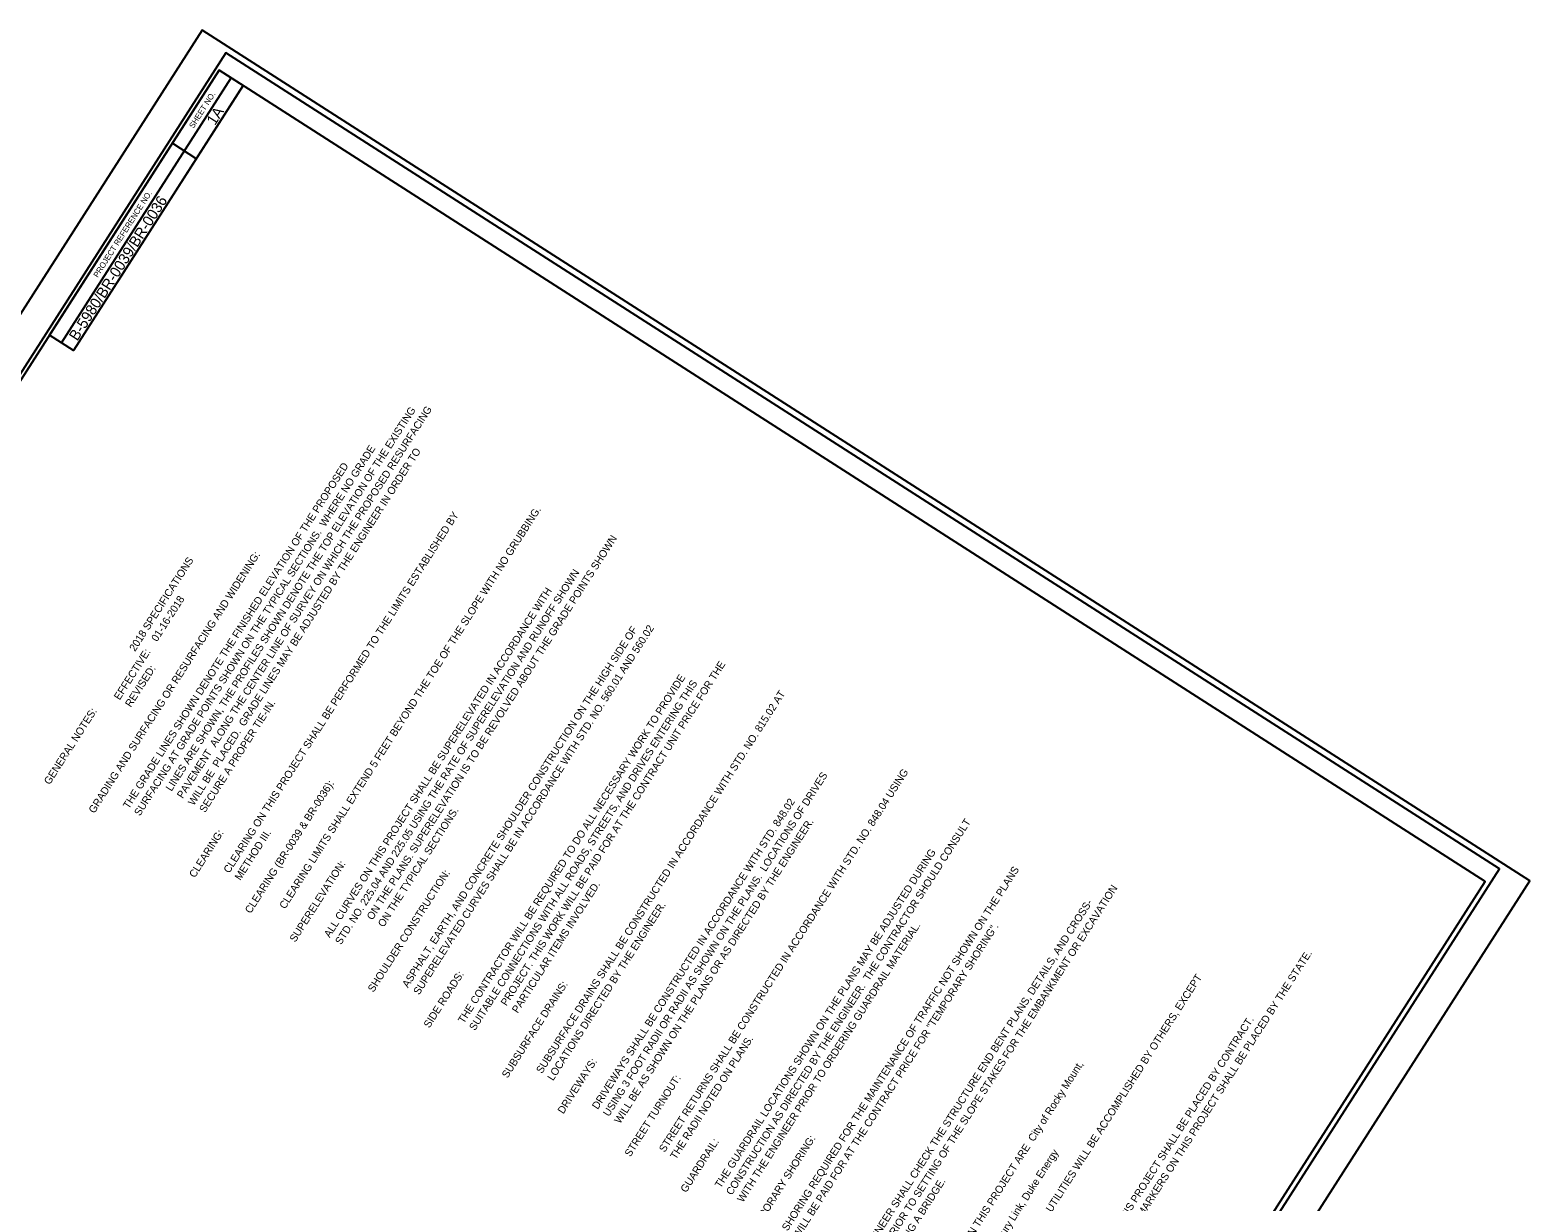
# Model space of a CAD drawing. Extents: x 2347249 to 2361994, y 830101 to 846299.
# Drawn here: x 2353623 to 2361994, y 839761 to 846299 of the extents above; entities that cross this region are included whole.
import ezdxf

# ---------------------------------------------------------------- set-up
doc = ezdxf.new("R2010")
doc.units = 0
for name, color, linetype in [('Sheet Data Field CELL', 7, 'Continuous'), ('Sheet Plot Border Inside CELL', 7, 'Continuous'), ('Sheet Plot Border Outside CELL', 7, 'Continuous'), ('Sheet Symbology CELL', 7, 'Continuous')]:
    doc.layers.add(name, color=color, linetype=linetype)

msp = doc.modelspace()

# ---------------------------------------------------------------- linework, layer by layer
at = {"layer": 'Sheet Plot Border Inside CELL'}
msp.add_lwpolyline([(2354564.1, 830285.9), (2361823.6, 841618.9), (2354715.9, 846171.7), (2347456.5, 834838.7)], close=True, dxfattribs=at)
at = {"layer": 'Sheet Plot Border Outside CELL'}
msp.add_lwpolyline([(2354658.7, 830100.6), (2361994.4, 841552.6), (2354584.3, 846299.2), (2347248.6, 834847.2)], close=True, dxfattribs=at)
at = {"layer": 'Sheet Symbology CELL'}
for p, q in [((2353799.3, 844554.1), (2354746.3, 846032.4)), ((2354116.5, 844900.9), (2354813.6, 845989.2)), ((2354417.5, 845667.5), (2354552.3, 845581.2))]:
    msp.add_line(p, q, dxfattribs=at)
for points in [[(2354678.6, 846075.7), (2348144.5, 835875), (2355211, 831348.5), (2361745.1, 841549.2)], [(2353731.7, 844597.4), (2354678.6, 846075.7), (2354813.6, 845989.2), (2353866.7, 844511)]]:
    msp.add_lwpolyline(points, close=True, dxfattribs=at)

# ---------------------------------------------------------------- texts
at = {"layer": 'Sheet Data Field CELL'}
for s, height, p in [('1A', 60, (2354655.1, 845763.4)), ('B-5980/BR-0039/BR-0036', 60, (2353886.9, 844560.6)), ('LINES ARE SHOWN, THE PROFILES SHOWN DENOTE THE TOP ELEVATION OF THE EXISTING ', 42, (2354412.7, 842048.7)), ('PAVEMENT  ALONG THE CENTER LINE OF SURVEY ON WHICH THE PROPOSED RESURFACING ', 42, (2354475, 842008.8)), ('        SURFACING AT GRADE POINTS SHOWN ON THE TYPICAL SECTIONS.  WHERE NO GRADE ', 42, (2354169.1, 841805.7)), ('WILL BE  PLACED.  GRADE LINES MAY BE ADJUSTED BY THE ENGINEER IN ORDER TO ', 42, (2354537.3, 841968.9)), ('        THE GRADE LINES SHOWN DENOTE THE FINISHED ELEVATION OF THE PROPOSED ', 42, (2354106.8, 841845.6)), ('        CLEARING ON THIS PROJECT SHALL BE PERFORMED TO THE LIMITS ESTABLISHED BY ', 42, (2354667.7, 841486.4)), ('        CLEARING LIMITS SHALL EXTEND 5 FEET BEYOND THE TOE OF THE SLOPE WITH NO GRUBBING.', 42, (2354979.3, 841286.8)), ('ON THE PLANS. SUPERELEVATION IS TO BE REVOLVED ABOUT THE GRADE POINTS SHOWN ', 42, (2355534.4, 841330.2)), ('GENERAL NOTES:                         2018 SPECIFICATIONS', 42, (2353732.9, 842085.2)), ('GRADING AND SURFACING OR RESURFACING AND WIDENING:  ', 42, (2353982.1, 841925.5)), ('        STD. NO. 225.04 AND 225.05 USING THE RATE OF SUPERELEVATION AND RUNOFF SHOWN ', 42, (2355290.9, 841087.2)), ('        ALL CURVES ON THIS PROJECT SHALL BE SUPERELEVATED IN ACCORDANCE WITH', 42, (2355228.5, 841127.1)), ('                                       EFFECTIVE:    01-16-2018', 42, (2353795.2, 842045.2)), ('        ASPHALT, EARTH, AND CONCRETE SHOULDER CONSTRUCTION ON THE HIGH SIDE OF', 42, (2355664.8, 840847.7)), ('        SUPERELEVATED CURVES SHALL BE IN ACCORDANCE WITH STD. NO. 560.01 AND 560.02', 42, (2355727.1, 840807.7)), ('                                       REVISED:      ', 42, (2353857.5, 842005.3)), ('PROJECT. THIS WORK WILL BE PAID FOR AT THE CONTRACT UNIT PRICE FOR THE ', 42, (2356282.3, 840851.2)), ('        THE CONTRACTOR WILL BE REQUIRED TO DO ALL NECESSARY WORK TO PROVIDE ', 42, (2355976.4, 840648.1)), ('        SUITABLE CONNECTIONS WITH ALL ROADS, STREETS, AND DRIVES ENTERING THIS ', 42, (2356038.7, 840608.1)), ('        SUBSURFACE DRAINS SHALL BE CONSTRUCTED IN ACCORDANCE WITH STD. NO. 815.02 AT ', 42, (2356412.6, 840368.6)), ('SECURE A PROPER TIE-IN.  ', 42, (2354599.6, 841929)), ('        USING 3 FOOT RADII OR RADII AS SHOWN ON THE PLANS.  LOCATIONS OF DRIVES', 42, (2356786.6, 840129.1)), ('        STREET RETURNS SHALL BE CONSTRUCTED IN ACCORDANCE WITH STD. NO. 848.04 USING ', 42, (2357098.2, 839929.5)), ('CLEARING (BR-0039 & BR-0036):  ', 42, (2354854.6, 841366.6)), ('        DRIVEWAYS SHALL BE CONSTRUCTED IN ACCORDANCE WITH STD. 848.02', 42, (2356724.2, 840169)), ('ON THE TYPICAL SECTIONS.  ', 42, (2355596.7, 841290.3)), ('CLEARING:  ', 42, (2354543, 841566.2)), ('        METHOD III.', 42, (2354730, 841446.5)), ('        WILL BE AS SHOWN ON THE PLANS OR AS DIRECTED BY THE ENGINEER.  ', 42, (2356848.9, 840089.2)), ('        CONSTRUCTION AS DIRECTED BY THE ENGINEER.  THE CONTRACTOR SHOULD CONSULT', 42, (2357472.1, 839690)), ('SUPERELEVATION:  ', 42, (2355103.9, 841206.9)), ('        THE GUARDRAIL LOCATIONS SHOWN ON THE PLANS MAY BE ADJUSTED DURING ', 42, (2357409.8, 839729.9)), ('SHOULDER CONSTRUCTION:  ', 42, (2355540.1, 840927.5)), ('        SHORING REQUIRED FOR THE MAINTENANCE OF TRAFFIC NOT SHOWN ON THE PLANS ', 42, (2357783.7, 839490.4)), ('PARTICULAR ITEMS INVOLVED.  ', 42, (2356344.6, 840811.2)), ('        SECTION PRIOR TO SETTING OF THE SLOPE STAKES FOR THE EMBANKMENT OR EXCAVATION ', 42, (2358219.9, 839211)), ('        LOCATIONS DIRECTED BY THE ENGINEER.  ', 42, (2356474.9, 840328.7)), ('        THE ENGINEER SHALL CHECK THE STRUCTURE END BENT PLANS, DETAILS, AND CROSS-', 42, (2358157.6, 839250.9)), ('        WITH THE ENGINEER PRIOR TO ORDERING GUARDRAIL MATERIAL.', 42, (2357534.4, 839650.1)), ('        WILL BE PAID FOR AT THE CONTRACT PRICE FOR "TEMPORARY SHORING".', 42, (2357846, 839450.5)), ('BR-0036/BR-0039 :RIGHT-OF-WAY MARKERS ON THIS PROJECT SHALL BE PLACED BY THE STATE.  ', 42, (2359336, 838895.1)), ('SIDE ROADS:  ', 42, (2355851.7, 840727.9)), ('SUBSURFACE DRAINS:', 42, (2356288, 840448.5)), ('        ANY RELOCATION OF EXISTING UTILITIES WILL BE ACCOMPLISHED BY OTHERS, EXCEPT ', 42, (2358780.8, 838851.7)), ('        B-5980: RIGHT-OF-WAY MARKERS ON THIS PROJECT SHALL BE PLACED BY CONTRACT.', 42, (2359092.4, 838652.1)), ('        THE RADII NOTED ON PLANS.  ', 42, (2357160.5, 839889.6)), ('DRIVEWAYS:  ', 42, (2356599.6, 840248.9)), ('        UTILITY OWNERS ON THIS PROJECT ARE  City of Rocky Mount, ', 42, (2358531.5, 839011.4)), ('STREET TURNOUT:  ', 42, (2356973.5, 840009.3)), ('GUARDRAIL:  ', 42, (2357285.1, 839809.7)), ('TEMPORARY SHORING:  ', 42, (2357659, 839570.2)), ('        Time Warner Cable, Century Link, Duke Energy', 42, (2358656.2, 838931.5)), ('        APPROACHING A BRIDGE.  ', 42, (2358282.2, 839171))]:
    msp.add_text(s, height=height, rotation=57.35811, dxfattribs=at).set_placement(p)
at = {"layer": 'Sheet Symbology CELL'}
for s, p in [('SHEET NO.', (2354535.4, 845747.7)), ('PROJECT REFERENCE NO.', (2354001.4, 844915.2))]:
    msp.add_text(s, height=32, rotation=57.35811, dxfattribs=at).set_placement(p)

doc.saveas('drawing.dxf')
